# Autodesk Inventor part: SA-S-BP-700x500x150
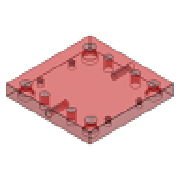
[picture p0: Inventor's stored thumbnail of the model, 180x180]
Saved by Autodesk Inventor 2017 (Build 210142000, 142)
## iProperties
Created: 2016-02
Part Number: SA-S-BP-700x500x150
Material: S 55 C
Description: Core Plate
Document SubType Name: Modeling
Designer: Sandeep
Standard Revision: 1
Manufacturer: FUTABA
Language: en-US
Size Designation: 700x500x150
Categories: <MemberInstance><Categories><Category DisplayName="Mold" InternalName="349578f2-f4d4-4954-8c09-8e99297a61c0" Mnemonic="MOLD"><Category DisplayName="Mold Plates"
Density: 7.85 g/cm^3
Appearance: Dark Red
IsCustomPart: 1
Author: Sandeep
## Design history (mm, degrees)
sketch "Sketch1"
  geometry: L1 (-250, 350)-(250, 350); L2 (250, 350)-(250, -350); L3 (250, -350)-(-250, -350); L4 (-250, -350)-(-250, 350); 7 further points
  constraints: 8 end point, 2 horizontal alignment, 2 midpoint, 2 parallel, 1 horizontal, 1 perpendicular, 1 vertical alignment
  dimensions: "d123" = 500 distance between parallel lines of L2 L4 (= W_); "d124" = 700 distance between parallel lines of L3 L1 (= L); "d125" = 317 vertical distance of point (0, 0) point (-128, 317) (= 0.5 x RP_L); "d126" = 128 horizontal distance of point (0, 0) point (-128, 317) (= 0.5 x RP_W); "d127" = 207 horizontal distance of point (0, 0) point (-207, 307) (= 0.5 x GP_W); "d128" = 307 vertical distance of point (0, 0) point (-207, 307) (= 0.5 x GP_L); "d129" = 205 horizontal distance of point (0, 0) point (-205, 243) (= 0.5 x S1_W); "d130" = 243 vertical distance of point (0, 0) point (-205, 243) (= 0.5 x S1_L); "d140" = 207 horizontal distance of point (207, 307) point (0, 0) (= 0.5 x GP_W)
extrude "Extrusion1" new body sketch "Sketch1" distance "d20" = 150 (= H_); taper "d30" = 0 deg
feature "Sculpt3"
body "Solid1"
sketch "Sketch2"
  geometry: L1 (500, 0)-(0, 0) reference; 3 further points
  constraints: 1 midpoint, 1 vertical alignment
  dimensions: "d186" = 75 distance from line of L1 point (250, 75) (= 0.5 x H_)
hole "Hole1" sketch "Sketch2" diameter "d104" = 31.67; stored, may be unused: countersink angle "d108" = 90 deg, drill point angle "d110" = 118 deg; dims "d105" = 59 (= le), "d106" = 46 (= GP_d2), "d107" = 10 (= GP_k), "d109" = 82 (= ke)
sketch "Sketch3"
  geometry: L1 (0, 0)-(500, 0) reference; 3 further points
  constraints: 1 midpoint, 1 vertical alignment
  dimensions: "d187" = 75 distance from line of point (250, -75) L1 (= 0.5 x H_)
hole "Hole2" sketch "Sketch3" diameter "d113" = 31.67; stored, may be unused: countersink angle "d117" = 90 deg, drill point angle "d119" = 118 deg; dims "d114" = 59 (= le), "d115" = 46 (= GP_d2), "d116" = 10 (= GP_k), "d118" = 82 (= ke)
hole "Hole3" sketch "Sketch1" diameter "d131" = 13.835; stored, may be unused: countersink angle "d135" = 90 deg, drill point angle "d137" = 118 deg; dims "d132" = 20 (= H_l), "d133" = 4, "d134" = 2, "d136" = 30 (= H_u)
pattern_linear "Rectangular Pattern1" dims "d164" = 243 (computed from S1_L, Ns), "d167" = 410 (computed from S1_W, Nw)
hole "Hole4" sketch "Sketch1" diameter "d141" = 40 (= GP_d1); stored, may be unused: countersink angle "d145" = 90 deg, drill point angle "d147" = 0 deg; dims "d142" = 6, "d143" = 46 (= GP_d2), "d144" = 10 (= GP_k), "d146" = 150 (= H_)
pattern_linear "Rectangular Pattern2" dims "d170" = 614 (computed from GP_L, Nl)
hole "Hole5" sketch "Sketch1" diameter "d148" = 40 (= GP_d1); stored, may be unused: countersink angle "d152" = 90 deg, drill point angle "d154" = 0 deg; dims "d149" = 6, "d150" = 46 (= GP_d2), "d151" = 10 (= GP_k), "d153" = 150 (= H_)
pattern_linear "Rectangular Pattern3" dims "d173" = 612 (computed from GP_L2, GP_L1, Nl)
hole "Hole6" sketch "Sketch1" diameter "d155" = 30 (= RP_dt); stored, may be unused: countersink angle "d159" = 90 deg, drill point angle "d161" = 0 deg; dims "d156" = 6, "d157" = 46 (= GP_d2), "d158" = 10 (= GP_k), "d160" = 150 (= H_)
pattern_linear "Rectangular Pattern4" dims "d176" = 634 (computed from RP_L, Nl), "d179" = 256 (computed from RP_W, Nw)
chamfer "Chamfer1" distance "d180" = 0.5; stored, may be unused: second distance "d181" = 2, angle "d182" = 45 deg
feature "Surface3"
body "Srf3"
other parameters: "L" = 700 [user parameter; used in 1 equation term], "W_" = 500 [user parameter; used in 3 equation terms], "H_" = 150 [user parameter; used in 8 equation terms], "GP_W" = 414 [user parameter; used in 2 equation terms], "GP_d1" = 40 [user parameter; used in 2 equation terms], "GP_d2" = 46 [user parameter; used in 5 equation terms], "GP_k" = 10 [user parameter; used in 5 equation terms], "S1_L" = 486 [user parameter; used in 2 equation terms], "GP_L1" = 307 [user parameter; used in 1 equation term], "GP_L2" = 305 [user parameter; used in 1 equation term], "RP_L" = 634 [user parameter; used in 2 equation terms], "RP_W" = 256 [user parameter; used in 2 equation terms], "RP_dt" = 30 [user parameter; used in 1 equation term], "GP_L" = 614 [user parameter; used in 2 equation terms], "d102" = 75 (= 0.5 x H_), "d112" = 75 (= 0.5 x H_), "le" = 59 [user parameter; used in 2 equation terms], "ke" = 82 [user parameter; used in 2 equation terms], "H_l" = 20 [user parameter; used in 1 equation term], "H_u" = 30 [user parameter; used in 1 equation term]
